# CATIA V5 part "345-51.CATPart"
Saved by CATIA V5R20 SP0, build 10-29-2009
Part number: 345-51
Definition: NONE
Nomenclature: 345-51
Source: Unknown
Description: 345-51
Bounding box of the stored display mesh (mm): x 0 to 100, y -51.5 to 51.5, z -51.5 to 51.5
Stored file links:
  C:\Users\Utente\Desktop\IO LAVORO\3D X SITO CF\X SITO\345-346\345-51.CATPart
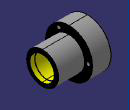
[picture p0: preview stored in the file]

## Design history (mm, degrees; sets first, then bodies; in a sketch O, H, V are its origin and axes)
Body1 "345-51" (main body)
  Solid1: solid without history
